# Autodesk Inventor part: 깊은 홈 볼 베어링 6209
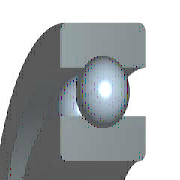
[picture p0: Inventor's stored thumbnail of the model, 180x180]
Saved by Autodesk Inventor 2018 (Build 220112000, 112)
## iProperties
IsCustomPart: 1
Created: 2012-02
Part Number: 깊은 홈 볼 베어링 6209
Material: 강철, 연강
Description: 깊은 그루부 볼 베어링
Document SubType Name: Modeling
Standard: JIS B 1521
Designer: mdu-01
Standards Organization: JIS
Language: ko-KR
Size Designation: 6209 45x85x19
Categories: <MemberInstance><Categories><Category DisplayName="샤프트 부품" InternalName="7f7aeb1f-a693-4053-b835-cee3144e0d98" Mnemonic="SHFT"><Category DisplayName="베어링" Inter
Density: 1 g/cm^3
Appearance: 강철(1)
Author: mdu-01
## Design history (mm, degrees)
sketch "스케치" dims "d0" = 10.4 (= -0.26 x WD + 0.26 x BD)
  geometry: L1 (4.3, 32.5)-(14.7, 32.5); L2 (9.5, 32.5)-(9.5, 27.3); L3 (9.5, 32.5)-(9.5, 37.7); L4 (5.636, 29.02)-(0, 29.02); L5 (0, 22.5)-(19, 22.5); L6 (5.636, 35.98)-(0, 35.98); L7 (0, 42.5)-(19, 42.5); L8 (19, 22.5)-(19, 29.02); L9 (13.364, 29.02)-(19, 29.02); L10 (13.364, 35.98)-(19, 35.98); L11 (19, 42.5)-(19, 35.98); L12 (-1.4, 0)-(8.4, 0) reference; L13 (0, -0.3)-(0, 5.3) reference
  constraints: 22 end point, 4 point on line, 2 collinear, 2 perpendicular, 2 symmetric about line, 1 midpoint, 1 parallel, 14 other
  dimensions: "d9" = 45 diameter of L5 L12 (= WD); "d11" = 85 diameter of L7 L12 (= BD); "d12" = 19 distance between parallel lines of L8 L13 (= KB); "d13" = 58.04 diameter of L9 L12 (= 0.326 x BD + 0.674 x WD)
revolve "본체" stored, may be unused: angle "d6" = 90 deg
revolve "볼" stored, may be unused: angle "d7" = 90 deg
pattern_circular "IDS_ARRAYBALL[SIMPL:T]" dims angle "d3" = 360 deg
body "Solid1"
fillet "모깎기1" dims "d1" = 1.1 (= KRS)
other parameters: "WD" = 45 [user parameter; used in 5 equation terms], "BD" = 85 [user parameter; used in 5 equation terms], "KB" = 19 [user parameter; used in 1 equation term], "KRS" = 1.1 [user parameter; used in 1 equation term], "d4" = 0, "d5" = 0, "d8" = 0, "d14" = 0, "d15" = 0, "BBA" = 0 [user parameter], "BC0" = 2.16e+07 [user parameter], "BC" = 3.32e+07 [user parameter], "BR" = 42.5 (= 0.5 x BD) [user parameter], "WR" = 22.5 (= 0.5 x WD) [user parameter]
